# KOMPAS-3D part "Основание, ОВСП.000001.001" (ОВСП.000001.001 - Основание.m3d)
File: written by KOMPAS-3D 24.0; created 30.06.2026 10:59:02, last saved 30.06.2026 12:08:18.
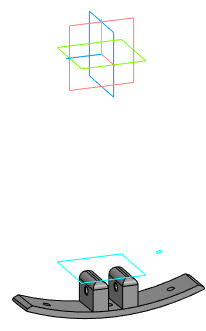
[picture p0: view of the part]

Document properties: Автор: Админ; Полное имя файла: C:\Users\Админ\Documents\ОВСП.000001.001 - Основание.m3d

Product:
- Part/product: Основание  | designation ОВСП.000001.001
    Масса: 0.267645

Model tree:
1. Смещенная плоскость:1  (labels: C:\Users\Админ\Desktop\Лопата\Лопата\КОМПАС\Сборка.a3d)
     Расстояние = -166
2. Эскиз:1  (labels: C:\Users\Админ\Desktop\Лопата\Лопата\КОМПАС\Сборка.a3d)
3. Элемент выдавливания:2
     Расстояние 2 = 25
4. Скругление:2  (with: Ребро.Элемент выдавливания:2)
     Радиус = 5
5. Эскиз:2  (with: Грань.Элемент выдавливания:2, Вершина.Скругление:2, Ребро.Элемент выдавливания:2)
6. Элемент выдавливания:3
     Расстояние 2 = 48
7. Фаска:3  (with: Ребро.Элемент выдавливания:3)
     Угол = 45; Длина 1 = 0.5; Длина 2 = 0.5
8. Эскиз:6  (labels: C:\Users\Админ\Desktop\Лопата\Лопата\КОМПАС\Сборка.a3d)
9. Элемент вращения:1  (labels: C:\Users\Админ\Desktop\Лопата\Лопата\КОМПАС\Сборка.a3d)
     Угол 1 = 42
10. Смещенная плоскость:2  (labels: Болт М5-6gx22 ГОСТ 7805-70; C:\Users\Админ\Desktop\Лопата\Лопата\КОМПАС\Сборка.a3d)
     Расстояние = -53
11. Эскиз:7  (with: Ребро. Фаска:1)  (labels: Болт М5-6gx22 ГОСТ 7805-70; C:\Users\Админ\Desktop\Лопата\Лопата\КОМПАС\Сборка.a3d)
12. Элемент выдавливания:5
     Расстояние 2 = 41
13. Зеркальный массив:1
14. Экземпляр ( 1 )
15. Экземпляр ( 2 )  (with: Элемент выдавливания:5)  (labels: C:\Users\Админ\Desktop\Лопата\Лопата\КОМПАС\Сборка.a3d)
16. Эскиз:8  (labels: C:\Users\Админ\Desktop\Лопата\Лопата\КОМПАС\Сборка.a3d; Вершина.Элемент выдавливания:5.Экземпляр ( 2 ))
17. Элемент выдавливания:6
     Расстояние 2 = 1000
18. Фаска:4  (with: Ребро.Элемент вращения:1)
     Угол = 45; Длина 1 = 3; Длина 2 = 3

Expressions: v116/2
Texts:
  ОВСП.000001.001
  Плоскость ZX.Начало координат
  Плоскость XY.Начало координат
  Ось X.Начало координат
